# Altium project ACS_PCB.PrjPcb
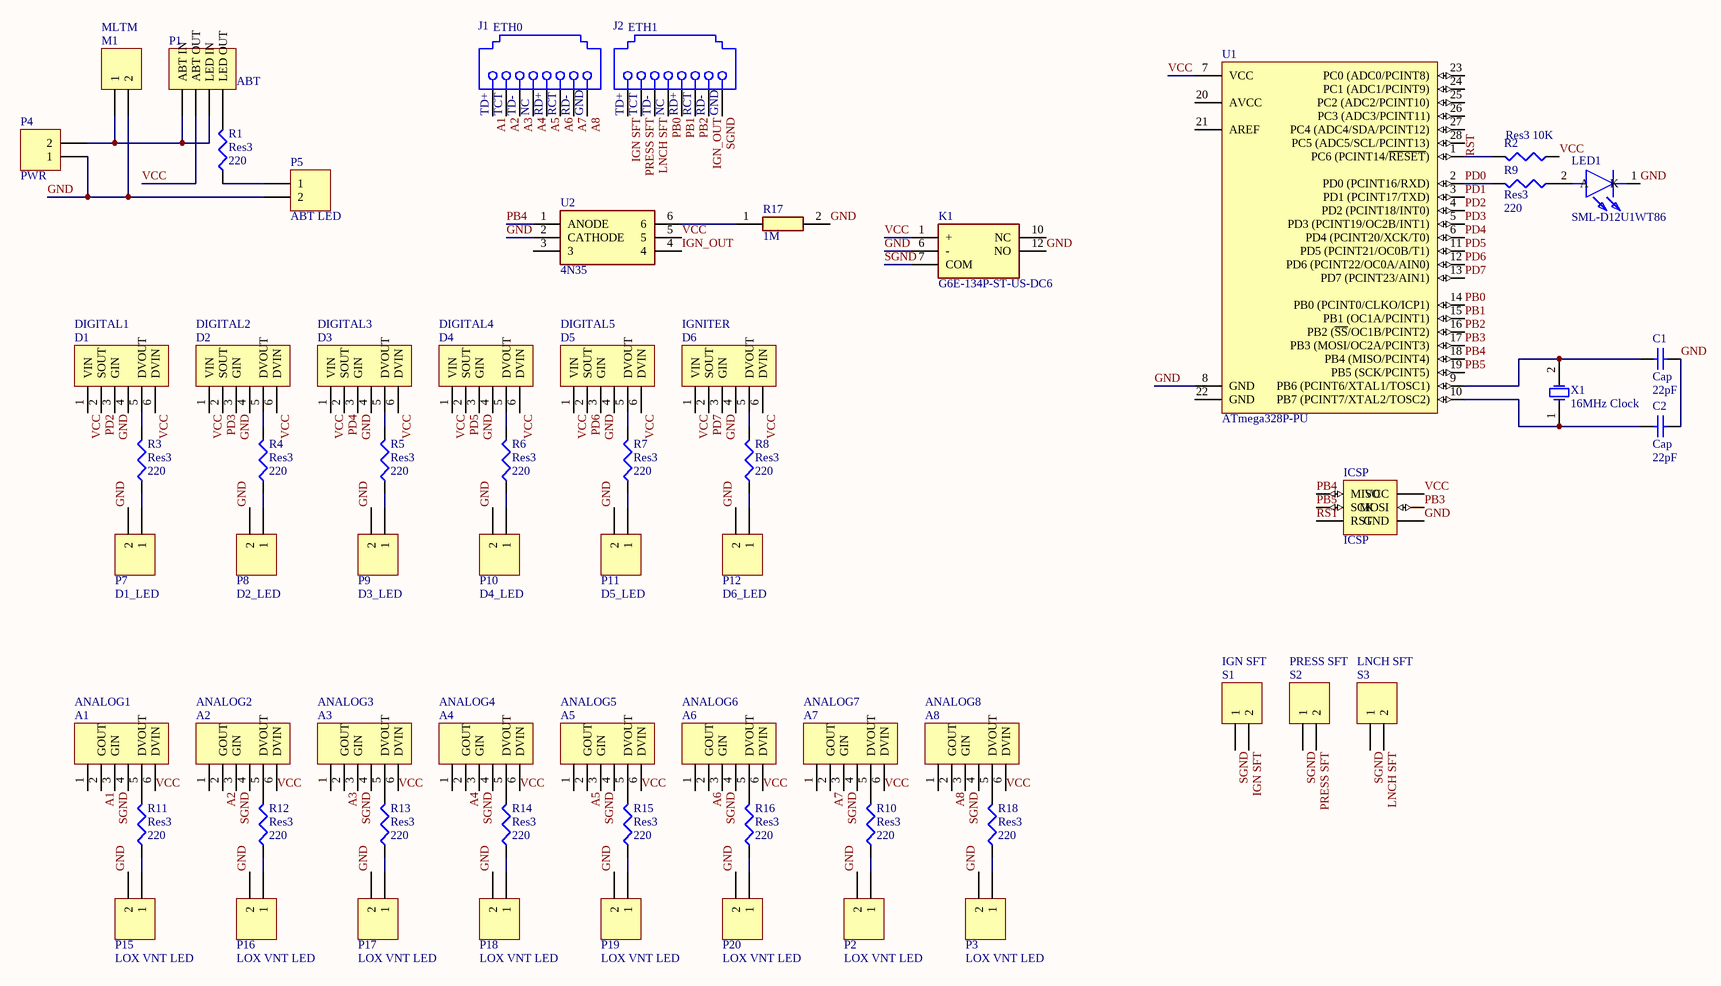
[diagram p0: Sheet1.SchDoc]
1 sheet, 63 parts. Net scope: global (net labels, ports and power ports of the same name join across sheets).
Board file: PCB2.PcbDoc

## Sheet Sheet1.SchDoc
size C

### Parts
A1  ANALOG1  [HDR1X6]
A2  ANALOG2  [HDR1X6]
A3  ANALOG3  [HDR1X6]
A4  ANALOG4  [HDR1X6]
A5  ANALOG5  [HDR1X6]
A6  ANALOG6  [HDR1X6]
A7  ANALOG7  [HDR1X6]
A8  ANALOG8  [HDR1X6]
C1  Cap  value 22pF  [RAD-0.3]
C2  Cap  value 22pF  [RAD-0.3]
D1  DIGITAL1  [HDR1X6]
D2  DIGITAL2  [HDR1X6]
D3  DIGITAL3  [HDR1X6]
D4  DIGITAL4  [HDR1X6]
D5  DIGITAL5  [HDR1X6]
D6  IGNITER  [HDR1X6]
ICSP  ICSP  [HDR2X3]
J1  ETH0  [TECO-5555153-1_V]
J2  ETH1  [TECO-5555153-1_V]
K1  G6E-134P-ST-US-DC6  [G6E-134P-US]
LED1  SML-D12U1WT86  [LEDC1608X65N]
M1  MLTM  [HDR1X2]
P1  ABT  [HDR1X4]
P2  LOX VNT LED  [HDR1X2]
P3  LOX VNT LED  [HDR1X2]
P4  PWR  [HDR1X2]
P5  ABT LED  [HDR1X2]
P7  D1_LED  [HDR1X2]
P8  D2_LED  [HDR1X2]
P9  D3_LED  [HDR1X2]
P10  D4_LED  [HDR1X2]
P11  D5_LED  [HDR1X2]
P12  D6_LED  [HDR1X2]
P15  LOX VNT LED  [HDR1X2]
P16  LOX VNT LED  [HDR1X2]
P17  LOX VNT LED  [HDR1X2]
P18  LOX VNT LED  [HDR1X2]
P19  LOX VNT LED  [HDR1X2]
P20  LOX VNT LED  [HDR1X2]
R1  Res3  value 220  [*RESC3146X60N]
R2  Res3  value 10K  [*RESC3146X60N]
R3  Res3  value 220  [*RESC3146X60N]
R4  Res3  value 220  [*RESC3146X60N]
R5  Res3  value 220  [*RESC3146X60N]
R6  Res3  value 220  [*RESC3146X60N]
R7  Res3  value 220  [*RESC3146X60N]
R8  Res3  value 220  [*RESC3146X60N]
R9  Res3  value 220  [*RESC3146X60N]
R10  Res3  value 220  [*RESC3146X60N]
R11  Res3  value 220  [*RESC3146X60N]
R12  Res3  value 220  [*RESC3146X60N]
R13  Res3  value 220  [*RESC3146X60N]
R14  Res3  value 220  [*RESC3146X60N]
R15  Res3  value 220  [*RESC3146X60N]
R16  Res3  value 220  [*RESC3146X60N]
R17  1M  [RESAD1550W60L630D230]
R18  Res3  value 220  [*RESC3146X60N]
S1  IGN SFT  [HDR1X2]
S2  PRESS SFT  [HDR1X2]
S3  LNCH SFT  [HDR1X2]
U1  ATmega328P-PU  [28P3]
U2  4N35  [DIP762W50P254L712H450Q6N]
X1  16MHz Clock  [CFM-HCM49-2_V]

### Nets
A1: A1.2(GOUT) J1.1
A2: A2.2(GOUT) J1.2
A3: A3.2(GOUT) J1.3
A4: A4.2(GOUT) J1.4
A5: A5.2(GOUT) J1.5
A6: A6.2(GOUT) J1.6
A7: A7.2(GOUT) J1.7
A8: A8.2(GOUT) J1.8
GND: C1.2 C2.2 D1.3(GIN) D2.3(GIN) D3.3(GIN) D4.3(GIN) D5.3(GIN) D6.3(GIN) ICSP.6(GND) K1.6(-) K1.12(NO) LED1.1(K) M1.2 P2.2 P3.2 P4.1 P5.2 P7.2 P8.2 P9.2 P10.2 P11.2 P12.2 P15.2 P16.2 P17.2 P18.2 P19.2 P20.2 R17.2 U1.8(GND) U2.2(CATHODE)
IGN SFT: J2.1 S1.2
IGN_OUT: J2.7 U2.4
LNCH SFT: J2.3 S3.2
PB0: J2.4 U1.14(PB0_(PCINT0/CLKO/ICP1))
PB1: J2.5 U1.15(PB1_(OC1A/PCINT1))
PB2: J2.6 U1.16(PB2_(~{SS}/OC1B/PCINT2))
PB3: ICSP.4(MOSI) U1.17(PB3_(MOSI/OC2A/PCINT3))
PB4: ICSP.1(MISO) U1.18(PB4_(MISO/PCINT4)) U2.1(ANODE)
PB5: ICSP.3(SCK) U1.19(PB5_(SCK/PCINT5))
PD0: R9.2 U1.2(PD0_(PCINT16/RXD))
PD1: U1.3(PD1_(PCINT17/TXD))
PD2: D1.2(SOUT) U1.4(PD2_(PCINT18/INT0))
PD3: D2.2(SOUT) U1.5(PD3_(PCINT19/OC2B/INT1))
PD4: D3.2(SOUT) U1.6(PD4_(PCINT20/XCK/T0))
PD5: D4.2(SOUT) U1.11(PD5_(PCINT21/OC0B/T1))
PD6: D5.2(SOUT) U1.12(PD6_(PCINT22/OC0A/AIN0))
PD7: D6.2(SOUT) U1.13(PD7_(PCINT23/AIN1))
PRESS SFT: J2.2 S2.2
RST: ICSP.5(RST) R2.2 U1.1(PC6_(PCINT14/~{RESET}))
SGND: A1.3(GIN) A2.3(GIN) A3.3(GIN) A4.3(GIN) A5.3(GIN) A6.3(GIN) A7.3(GIN) A8.3(GIN) J2.8 K1.7(COM) S1.1 S2.1 S3.1
VCC: A1.6(DVIN) A2.6(DVIN) A3.6(DVIN) A4.6(DVIN) A5.6(DVIN) A6.6(DVIN) A7.6(DVIN) A8.6(DVIN) D1.1(VIN) D1.6(DVIN) D2.1(VIN) D2.6(DVIN) D3.1(VIN) D3.6(DVIN) D4.1(VIN) D4.6(DVIN) D5.1(VIN) D5.6(DVIN) D6.1(VIN) D6.6(DVIN) ICSP.2(VCC) K1.1(+) P1.2(ABT_OUT) R2.1 U1.7(VCC) U2.5
NetA1_5: A1.5(DVOUT) R11.2
NetA2_5: A2.5(DVOUT) R12.2
NetA3_5: A3.5(DVOUT) R13.2
NetA4_5: A4.5(DVOUT) R14.2
NetA5_5: A5.5(DVOUT) R15.2
NetA6_5: A6.5(DVOUT) R16.2
NetA7_5: A7.5(DVOUT) R10.2
NetA8_5: A8.5(DVOUT) R18.2
NetC1_1: C1.1 U1.9(PB6_(PCINT6/XTAL1/TOSC1)) X1.2(X2)
NetC2_1: C2.1 U1.10(PB7_(PCINT7/XTAL2/TOSC2)) X1.1(X1)
NetD1_5: D1.5(DVOUT) R3.2
NetD2_5: D2.5(DVOUT) R4.2
NetD3_5: D3.5(DVOUT) R5.2
NetD4_5: D4.5(DVOUT) R6.2
NetD5_5: D5.5(DVOUT) R7.2
NetD6_5: D6.5(DVOUT) R8.2
NetLED1_2: LED1.2(A) R9.1
NetM1_1: M1.1 P1.1(ABT_IN) P1.3(LED_IN) P4.2
NetP1_4: P1.4(LED_OUT) R1.2
NetP2_1: P2.1 R10.1
NetP3_1: P3.1 R18.1
NetP5_1: P5.1 R1.1
NetP7_1: P7.1 R3.1
NetP8_1: P8.1 R4.1
NetP9_1: P9.1 R5.1
NetP10_1: P10.1 R6.1
NetP11_1: P11.1 R7.1
NetP12_1: P12.1 R8.1
NetP15_1: P15.1 R11.1
NetP16_1: P16.1 R12.1
NetP17_1: P17.1 R13.1
NetP18_1: P18.1 R14.1
NetP19_1: P19.1 R15.1
NetP20_1: P20.1 R16.1
NetR17_1: R17.1 U2.6

Not connected (* = marked no-connect by the designer): A1 1 4; A2 1 4; A3 1 4; A4 1 4; A5 1 4; A6 1 4; A7 1 4; A8 1 4; D1 4; D2 4; D3 4; D4 4; D5 4; D6 4; J1 S1 S2; J2 S1 S2; K1 10(NC); U1 20(AVCC) 21(AREF) 22(GND) 23(PC0_(ADC0/PCINT8)) 24(PC1_(ADC1/PCINT9)) 25(PC2_(ADC2/PCINT10)) 26(PC3_(ADC3/PCINT11)) 27(PC4_(ADC4/SDA/PCINT12)) 28(PC5_(ADC5/SCL/PCINT13)); U2 3

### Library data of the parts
A1-A8 D1-D6 = Header 6: Header, 6-Pin
C1 C2 = Cap: Capacitor
ICSP = Header 3X2: Header, 3-Pin, Dual row
J1 J2 = CMP-2000-05640-1: RJ45 Connector, Pitch 1.27 mm, 8 Position, Height 13.08 mm, Tail Length 3.81 mm, -40 to 85 degC, RoHS, Tray; Manufacturer: TE Connectivity; Number of Ports: 1; Shielding: Shielded; 3D Model: 5555153-1.pdf; Catalog Drawings: JackSideEntryRightAngle / JackSideEntryRightAngleTop; Ratings: Cat3; Connector Type: Jack; LED Color: DoesNotContainLED; Other Names: A31438; Tab Direction: Down; Number of Positions/Contacts: 8p8c(RJ45,Ethernet); Dynamic Catalog: ModularJacks
K1 = G6E-134P-ST-US-DC6: Relay or Contactor; Manufacturer_Name: Omron Electronics; Allied_Number: 70381892
LED1 = SML-D12U1WT86: LED; Manufacturer_Name: ROHM Semiconductor
M1 P2-P5 P7-P12 P15-P20 S1-S3 = Header 2: Header, 2-Pin
P1 = Header 4: Header, 4-Pin
R1-R16 R18 = Res3: Resistor
R17 = YR1B1M0CC: Resistor; Manufacturer_Name: TE Connectivity; Allied_Number: 70300029
U1 = CMP-0095-00013-2: 8-bit AVR Microcontroller, 32KB Flash, 1KB EEPROM, 2KB SRAM, 28-pin PDIP, Industrial Grade (-40°C to 85°C)
U2 = 4N35: Transistor; Manufacturer_Name: Isocom
X1 = CMP-1215-00001-1: At-Cut Crystal Unit, 3.5 to 30 MHz, -40 to 85 degC, 2-Pin 11.4Ã—4.7Ã—4.3 mm SMD, RoHS, Reel; Manufacturer: Citizen Finetech Miyota; PartNumber: HCM49-8.000MABJ-UT; DL: 100 uW; C0: 7 pF Max.; R1: 50 to 200 Ohm; IR: 500 MOhm Min.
